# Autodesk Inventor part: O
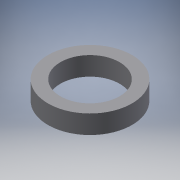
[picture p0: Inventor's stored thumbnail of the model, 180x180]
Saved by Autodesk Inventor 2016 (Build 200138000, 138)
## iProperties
Created: 2017-05
Part Number: O
Material: Glass
Document SubType Name: Modeling
Designer: 8643301
Density: 2.18 g/cm^3
Appearance: Clear
Author: 8643301
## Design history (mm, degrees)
sketch "Sketch1"
  geometry: C1 r 11.43 at (0, 0); C2 r 8.052 at (0, 0); 1 further point
  constraints: 2 centre point, 2 coincident
  dimensions: "d0" = 22.86 diameter of C1; "d1" = 16.1036 diameter of C2
extrude "Extrusion1" new body sketch "Sketch1" distance "d2" = 5.08; taper "d3" = 0 deg
body "Solid1"
